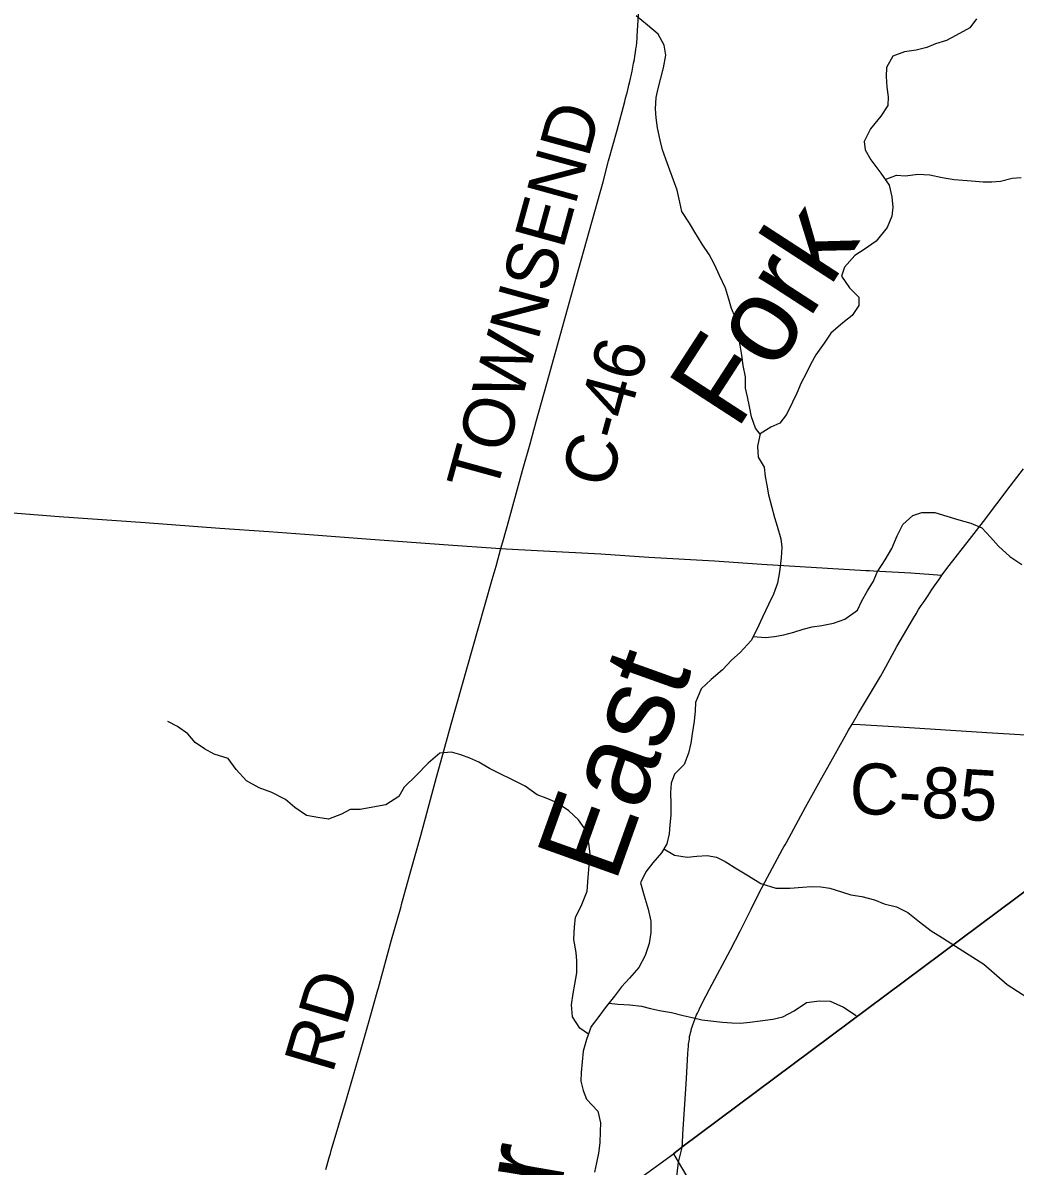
# Model space of a CAD drawing. Extents: x 0 to 48.6, y 0 to 22.
# Drawn here: x 3.311 to 4.415, y 15.882 to 17.154 of the extents above; entities that cross this region are included whole.
import ezdxf

# ---------------------------------------------------------------- set-up
doc = ezdxf.new("R2010")
doc.units = 0
for name, color, linetype in [('GM_X_Corporation', 7, 'Continuous'), ('GM_X_County_Road', 7, 'Continuous'), ('GM_X_County_Road_Text', 7, 'Continuous'), ('GM_X_Major_River', 7, 'Continuous'), ('GM_X_Major_River_Text', 7, 'Continuous'), ('GM_X_Minor_River', 7, 'Continuous'), ('GM_X_State_Route', 7, 'Continuous'), ('GM_X_Township_Road', 7, 'Continuous'), ('GM_X_Township_Road_Text', 7, 'Continuous')]:
    doc.layers.add(name, color=color, linetype=linetype)

msp = doc.modelspace()

# ---------------------------------------------------------------- linework, layer by layer
at = {"layer": 'GM_X_Corporation'}
msp.add_lwpolyline([(5.0944, 14.1), (8.9, 14.1), (8.9, 19.5692), (8.5348, 19.2897), (7.2261, 18.2847), (6.9471, 18.0777), (6.5365, 17.7727), (5.8387, 17.2541), (5.5264, 17.0064), (4.6225, 16.3345), (4.044, 15.9033), (4.0346, 15.8959), (4.0398, 15.887), (4.3544, 15.3539), (4.4679, 15.1616), (4.7542, 14.6766)], close=True, dxfattribs=at)
msp.add_lwpolyline([(3.9507, 15.8348), (4.0346, 15.8959), (4.044, 15.9033), (4.6225, 16.3345), (5.5264, 17.0064)], dxfattribs=at)
msp.add_lwpolyline([(3.9507, 15.8348), (4.0346, 15.8959), (4.044, 15.9033), (4.6225, 16.3345), (5.5264, 17.0064)], dxfattribs=at)
at = {"layer": 'GM_X_County_Road'}
for points in [[(3.8424, 16.5693), (3.8453, 16.5795), (3.8512, 16.6005), (3.8666, 16.6561), (3.8751, 16.686), (3.8817, 16.7106), (3.8935, 16.7531), (3.9035, 16.789), (3.926, 16.8692), (3.9562, 16.9775), (3.9624, 17.0009), (3.9718, 17.0351), (3.9804, 17.0668), (3.9813, 17.0704), (3.9823, 17.0742), (3.9832, 17.0778), (3.9849, 17.0851), (3.9859, 17.0891), (3.9866, 17.0923), (3.9873, 17.0953), (3.9884, 17.1006), (3.9894, 17.1049), (3.9902, 17.1094), (3.991, 17.1137), (3.9917, 17.1172), (3.9922, 17.1214), (3.9928, 17.1254), (3.9932, 17.1283), (3.9936, 17.133), (3.994, 17.1369), (3.9943, 17.1401), (3.9958, 17.1693)], [(3.2713, 16.6113), (3.3512, 16.605), (3.4466, 16.5982), (3.5297, 16.5922), (3.5842, 16.5882), (3.6344, 16.5845), (3.6976, 16.5797), (3.7837, 16.5735), (3.837, 16.5696), (3.8424, 16.5693)], [(3.8424, 16.5693), (3.8482, 16.569), (3.8898, 16.5668), (3.9536, 16.5633), (4.007, 16.5599), (4.0802, 16.5556), (4.1329, 16.5521), (4.2487, 16.5451), (4.2526, 16.5448), (4.2569, 16.5446), (4.2985, 16.5422), (4.3233, 16.5406), (4.3331, 16.5397)], [(4.2332, 16.374), (4.2422, 16.3734), (4.2856, 16.3708), (4.383, 16.3648), (4.4388, 16.3613), (4.4692, 16.3596), (4.5648, 16.3537), (4.5927, 16.3521), (4.6032, 16.3514), (4.6112, 16.3509), (4.6131, 16.3506), (4.6149, 16.3501), (4.6172, 16.3493), (4.6188, 16.3483), (4.6201, 16.347), (4.6212, 16.3455), (4.6217, 16.3444), (4.6221, 16.3432), (4.6224, 16.3421), (4.6228, 16.3408), (4.6229, 16.3381), (4.6228, 16.334)]]:
    msp.add_lwpolyline(points, dxfattribs=at)
at = {"layer": 'GM_X_Major_River'}
for points in [[(4.3717, 17.1588), (4.3643, 17.1487), (4.3486, 17.1403), (4.3382, 17.1348), (4.326, 17.1309), (4.3164, 17.1269), (4.3046, 17.1241), (4.2917, 17.1221), (4.2786, 17.1174), (4.2715, 17.1047), (4.271, 17.0948), (4.2718, 17.0827), (4.2735, 17.072), (4.2729, 17.0625), (4.2651, 17.0505), (4.2538, 17.0364), (4.2467, 17.0225), (4.2476, 17.013), (4.2542, 17.0018), (4.2653, 16.9872), (4.2745, 16.9737), (4.2776, 16.9607), (4.2785, 16.9493), (4.2775, 16.9391), (4.2723, 16.9267), (4.2602, 16.9114), (4.2468, 16.9022), (4.2364, 16.8955), (4.2247, 16.8825), (4.2215, 16.8723), (4.2303, 16.8596), (4.2407, 16.8492), (4.2409, 16.8397), (4.2334, 16.8288), (4.223, 16.8207), (4.2095, 16.8092), (4.2021, 16.7979), (4.193, 16.7848), (4.1871, 16.774), (4.182, 16.7642), (4.1764, 16.7537), (4.1717, 16.7424), (4.1669, 16.7322)], [(4.1669, 16.7322), (4.1601, 16.7187), (4.1527, 16.709), (4.1428, 16.7043), (4.1308, 16.6969), (4.1279, 16.6833), (4.1288, 16.6712), (4.1354, 16.66), (4.1367, 16.6494), (4.1384, 16.6398), (4.1404, 16.6292), (4.1436, 16.6166), (4.1471, 16.604), (4.1499, 16.5941), (4.1538, 16.5803), (4.1551, 16.5708), (4.1545, 16.5591), (4.1526, 16.5435), (4.1501, 16.5307), (4.1457, 16.5186), (4.1401, 16.507), (4.1334, 16.4931), (4.1274, 16.4792), (4.121, 16.4671), (4.1086, 16.4537), (4.0989, 16.4452), (4.0892, 16.4344), (4.0765, 16.4236), (4.0652, 16.4132), (4.0589, 16.3982), (4.0587, 16.3887), (4.0577, 16.3773), (4.0555, 16.363), (4.0537, 16.3528), (4.0512, 16.3418), (4.0464, 16.329), (4.0355, 16.3182), (4.0319, 16.3084), (4.0313, 16.2978), (4.0314, 16.2849), (4.0315, 16.2728), (4.0305, 16.2618), (4.0296, 16.2519), (4.0271, 16.2406), (4.0212, 16.2308), (4.0114, 16.2196), (4.0036, 16.2096), (3.9977, 16.1975), (4.0019, 16.1827), (4.0062, 16.1681), (4.0093, 16.1548), (4.0094, 16.1419), (4.0073, 16.1298), (4.0032, 16.1166), (3.9961, 16.1031), (3.9856, 16.0911), (3.9766, 16.0815), (3.9688, 16.0714), (3.9587, 16.0583), (3.9513, 16.0486), (3.9431, 16.0374), (3.9378, 16.023), (3.9341, 16.0102), (3.9331, 15.9981), (3.9317, 15.9864), (3.9315, 15.9765), (3.934, 15.9662), (3.9379, 15.9566), (3.9505, 15.9431), (3.9533, 15.9301), (3.9531, 15.9206), (3.9525, 15.9081), (3.9511, 15.8964), (3.949, 15.8858), (3.9468, 15.8752)]]:
    msp.add_lwpolyline(points, dxfattribs=at)
at = {"layer": 'GM_X_Minor_River'}
for points in [[(4.1308, 16.6966), (4.1259, 16.7035), (4.1212, 16.7161), (4.119, 16.7276), (4.1169, 16.7382), (4.1148, 16.7477), (4.1145, 16.7606), (4.1121, 16.7732), (4.1107, 16.7846), (4.1089, 16.7956), (4.1068, 16.8063), (4.1054, 16.8166), (4.1033, 16.8268), (4.0989, 16.8364), (4.096, 16.8467), (4.0923, 16.8593), (4.0857, 16.8734), (4.0801, 16.8856), (4.0742, 16.8967), (4.0664, 16.9082), (4.0582, 16.9216), (4.0523, 16.9315), (4.0437, 16.9445), (4.0416, 16.9548), (4.0387, 16.9681), (4.0347, 16.9792), (4.0303, 16.9906), (4.0259, 17.0025), (4.0222, 17.0131), (4.0197, 17.0238), (4.0169, 17.0375), (4.0151, 17.0485), (4.0145, 17.0588), (4.0154, 17.0713), (4.0174, 17.0815), (4.0203, 17.0929), (4.0234, 17.1042), (4.0259, 17.1183), (4.0242, 17.1297), (4.0175, 17.1419), (4.0055, 17.1519), (3.9931, 17.162)], [(4.2701, 16.9801), (4.2828, 16.9847), (4.2927, 16.9842), (4.3064, 16.9859), (4.3196, 16.9854), (4.3333, 16.9822), (4.3469, 16.9801), (4.3564, 16.9792), (4.3659, 16.9787), (4.3792, 16.9774), (4.3887, 16.9773), (4.3982, 16.9783), (4.4115, 16.9815), (4.4214, 16.9822)], [(4.1233, 16.4714), (4.1368, 16.4703), (4.1471, 16.4713), (4.1574, 16.4735), (4.1685, 16.4764), (4.1788, 16.4796), (4.189, 16.4822), (4.1997, 16.4839), (4.2127, 16.4864), (4.2252, 16.4908), (4.2394, 16.5009), (4.2441, 16.5111), (4.2504, 16.5224), (4.257, 16.5329), (4.2613, 16.5431), (4.2702, 16.5567), (4.2776, 16.5695), (4.2835, 16.5834), (4.2897, 16.5963), (4.3009, 16.606), (4.3108, 16.6093), (4.3252, 16.6095), (4.3388, 16.6055), (4.3521, 16.6012), (4.3653, 16.5976), (4.3774, 16.5925), (4.3871, 16.5821), (4.3961, 16.5721), (4.4089, 16.5606), (4.4221, 16.5517)], [(3.9399, 16.0288), (3.9304, 16.0357), (3.9223, 16.0483), (3.9209, 16.0616), (3.923, 16.0741), (3.9246, 16.0847), (3.9271, 16.0972), (3.9269, 16.1105), (3.9263, 16.12), (3.9238, 16.1344), (3.9244, 16.1485), (3.9256, 16.1587), (3.9327, 16.1731), (3.9386, 16.1882), (3.9395, 16.2033), (3.9409, 16.2166), (3.9421, 16.2268), (3.9404, 16.2413), (3.9376, 16.255), (3.929, 16.2676), (3.9181, 16.2776), (3.9042, 16.2866), (3.8929, 16.2916), (3.883, 16.2952), (3.8695, 16.3048), (3.8548, 16.3122), (3.8408, 16.3189), (3.8299, 16.3247), (3.8178, 16.3317), (3.808, 16.336), (3.7978, 16.3399), (3.7876, 16.3427), (3.7747, 16.3418), (3.7616, 16.3305), (3.7481, 16.3167), (3.735, 16.3039), (3.7288, 16.2934), (3.7146, 16.2841), (3.7002, 16.2816), (3.6861, 16.2788), (3.6747, 16.2789), (3.6651, 16.2737), (3.6506, 16.2682), (3.6388, 16.2699), (3.6263, 16.2723), (3.6132, 16.2812), (3.6027, 16.2901), (3.5876, 16.2979), (3.5736, 16.303), (3.5596, 16.3108), (3.548, 16.3234), (3.5391, 16.3357), (3.5236, 16.3405), (3.5126, 16.3463), (3.5025, 16.3536), (3.4942, 16.3632), (3.4826, 16.3714), (3.472, 16.3768)], [(4.0238, 16.2352), (4.0356, 16.2283), (4.0496, 16.2258), (4.0606, 16.2272), (4.072, 16.2278), (4.0823, 16.2258), (4.0921, 16.2211), (4.1049, 16.213), (4.1181, 16.2052), (4.1316, 16.1967), (4.1483, 16.1915), (4.1639, 16.1913), (4.1779, 16.1927), (4.1882, 16.1933), (4.1984, 16.1928), (4.2083, 16.1915), (4.2215, 16.1872), (4.2317, 16.184), (4.2439, 16.1823), (4.2583, 16.1783), (4.2688, 16.174), (4.2825, 16.1708), (4.2953, 16.1642), (4.3081, 16.1541), (4.3212, 16.1441), (4.3337, 16.136), (4.3441, 16.1296)], [(4.3441, 16.1296), (4.3797, 16.1069), (4.4056, 16.0842), (4.4289, 16.0695), (4.4992, 16.0481), (4.5212, 16.0524), (4.5628, 16.0645), (4.6078, 16.0578), (4.6567, 16.044)], [(3.9626, 16.0634), (3.9726, 16.0624), (3.9859, 16.0615), (3.9988, 16.0602), (4.009, 16.0574), (4.0188, 16.0554), (4.0325, 16.0529), (4.0453, 16.0497), (4.0552, 16.0473), (4.0662, 16.0449), (4.0889, 16.0423), (4.0995, 16.0414), (4.109, 16.0413), (4.1193, 16.0423), (4.1311, 16.0437), (4.1452, 16.0458), (4.1562, 16.0483), (4.1689, 16.055), (4.1827, 16.0643), (4.1971, 16.066), (4.2089, 16.0658), (4.2236, 16.0588), (4.2378, 16.0497)]]:
    msp.add_lwpolyline(points, dxfattribs=at)
at = {"layer": 'GM_X_State_Route'}
for points in [[(4.0443, 15.9028), (4.0445, 15.9076), (4.045, 15.9176), (4.0473, 15.9511), (4.049, 15.9796), (4.0505, 16.0075), (4.0508, 16.0117), (4.0512, 16.0155), (4.0514, 16.0181), (4.0518, 16.0212), (4.0522, 16.0238), (4.0525, 16.0262), (4.0531, 16.0287), (4.0534, 16.0305), (4.0541, 16.0328), (4.0547, 16.0351), (4.0553, 16.0371), (4.056, 16.0392), (4.0572, 16.0424), (4.0582, 16.0453), (4.0591, 16.0475), (4.0603, 16.0505), (4.0611, 16.0523), (4.0626, 16.0553), (4.064, 16.0582), (4.0652, 16.0607), (4.0666, 16.0634), (4.0746, 16.0789), (4.0979, 16.1228), (4.1088, 16.1437), (4.121, 16.1682), (4.1292, 16.1849), (4.1362, 16.198), (4.1559, 16.2347), (4.1573, 16.2373), (4.1586, 16.2396), (4.1605, 16.2429), (4.1815, 16.2815), (4.1964, 16.3081), (4.2148, 16.3412), (4.2293, 16.3673), (4.2332, 16.374), (4.2402, 16.3861), (4.2648, 16.4271), (4.2709, 16.4378), (4.2831, 16.4602), (4.3016, 16.4919), (4.3045, 16.4968), (4.3073, 16.5016), (4.3101, 16.5058), (4.3134, 16.5106), (4.3177, 16.517), (4.3217, 16.523), (4.325, 16.5279), (4.3296, 16.5346), (4.3328, 16.5391), (4.3331, 16.5397), (4.3357, 16.5431), (4.3388, 16.5472), (4.3413, 16.5506), (4.3638, 16.5796), (4.3795, 16.5996), (4.4091, 16.6388), (4.4238, 16.6581)], [(3.6785, 14.9709), (3.6813, 14.9916), (3.6889, 15.0268), (3.7036, 15.0771), (3.716, 15.119), (3.7243, 15.1527), (3.7475, 15.1836), (3.7699, 15.2102), (3.7914, 15.2335), (3.8031, 15.2519), (3.8721, 15.3307), (3.9352, 15.399), (3.968, 15.438), (3.9958, 15.4676), (4.0059, 15.4865), (4.0311, 15.8085), (4.04, 15.8865), (4.0443, 15.9028)]]:
    msp.add_lwpolyline(points, dxfattribs=at)
at = {"layer": 'GM_X_Township_Road'}
msp.add_lwpolyline([(3.6476, 15.8784), (3.6519, 15.8929), (3.6528, 15.8963), (3.6538, 15.8995), (3.6706, 15.9565), (3.6862, 16.0102), (3.6952, 16.0412), (3.705, 16.0757), (3.7057, 16.0783), (3.7063, 16.0806), (3.7209, 16.134), (3.7308, 16.1685), (3.7315, 16.1711), (3.7321, 16.1734), (3.7423, 16.2106), (3.7533, 16.2501), (3.771, 16.3148), (3.7761, 16.3334), (3.7873, 16.3741), (3.8173, 16.4799), (3.8328, 16.5349), (3.8372, 16.5498), (3.8424, 16.5693)], dxfattribs=at)

# ---------------------------------------------------------------- texts
at = {"layer": 'GM_X_County_Road_Text'}
for s, rotation, p in [('TOWNSEND', 74.606, (3.8366, 16.6287)), ('C-46', 74.6575, (3.9635, 16.6345)), ('C-85', 356.5725, (4.229, 16.2751))]:
    msp.add_text(s, height=0.05682, rotation=rotation, dxfattribs=at).set_placement(p)
at = {"layer": 'GM_X_Major_River_Text'}
for s, rotation, p in [('Fork', 57.0271, (4.1048, 16.6998)), ('East', 70.3043, (3.9695, 16.1956)), ('River', 80.1789, (3.8663, 15.6061))]:
    msp.add_text(s, height=0.0947, rotation=rotation, dxfattribs=at).set_placement(p)
at = {"layer": 'GM_X_Township_Road_Text'}
msp.add_text('RD', height=0.05682, rotation=73.5814, dxfattribs=at).set_placement((3.6551, 15.9839))

doc.saveas('drawing.dxf')
